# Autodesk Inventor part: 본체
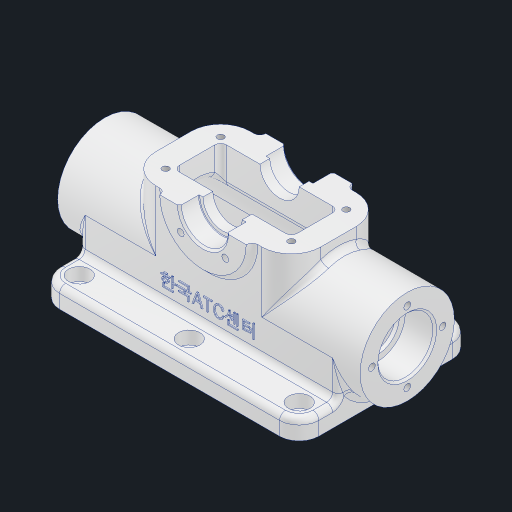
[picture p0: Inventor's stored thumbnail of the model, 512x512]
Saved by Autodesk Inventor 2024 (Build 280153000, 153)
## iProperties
Created: 2024-06
Part Number: 본체
Material: 알루미늄 6061
Document SubType Name: Modeling
Designer: kh_501
Density: 2.7 g/cm^3
Appearance: 알루미늄 - 평지
Mass: 551.028 g
Surface Area: 613.377 cm^2
Volume: 204.084 cm^3
Author: kh_501
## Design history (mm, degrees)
sketch "스케치1"
  geometry: L1 (66, 44)-(-66, 44); L2 (-66, 44)-(-66, -44); L3 (-66, -44)-(66, -44); L4 (66, -44)-(66, 44); L5 (66, 44)-(-66, -44); L6 (-66, 44)-(66, -44); 1 further point
  constraints: 12 end point, 2 midpoint, 2 parallel, 1 horizontal, 1 perpendicular
  dimensions: "d0" = 132 distance of L2.end L3.end; "d1" = 88 distance of L3.end L1.start
extrude "돌출1" new body sketch "스케치1" distance "d2" = 10; taper "d3" = 0 deg
sketch "스케치2"
  geometry: L1 (-77, 52)-(77, 52); L2 (77, 52)-(77, 28); L3 (77, 28)-(-77, 28); L4 (-77, 28)-(-77, 52); L5 (-66, 0)-(66, 0) reference; 3 further points
  constraints: 8 end point, 2 midpoint, 2 parallel, 1 horizontal, 1 perpendicular, 1 vertical alignment
  dimensions: "d4" = 28 distance between parallel lines of L5 L3; "d5" = 154 distance of L1.start L1.end; "d6" = 48 diameter of L1 L3
revolve "회전1" sketch "스케치2" stored, may be unused: angle "d7" = 90 deg
sketch "스케치3"
  geometry: L1 (-66, 44)-(-66, 15.875) reference; L2 (66, 15.875)-(66, 44) reference; L3 (77, 24)-(-77, 24) reference; L4 (77, -24)-(-77, -24) reference; L5 (-66, -15.875)-(-66, 15.875) reference; L6 (-66, -15.875)-(-66, -44) reference; L7 (66, 15.875)-(66, -15.875) reference; L8 (66, -44)-(66, 44) reference; L9 (-42, -24)-(42, -24); L10 (42, 24)-(-42, 24); 5 further points
  constraints: 4 end point, 1 horizontal, 1 parallel, 1 point on line
extrude "돌출2" join sketch "스케치3" stored distance "d9" = 18; taper "d10" = 0 deg
node "작업 평면1"
sketch "스케치4"
  geometry: L1 (-66, 24)-(66, 24) reference; L2 (-66, -24)-(66, -24) reference; L3 (-42, 24)-(42, 24); L4 (42, 24)-(42, -24); L5 (42, -24)-(-42, -24); L6 (-42, -24)-(-42, 24); L7 (-42, 24)-(42, -24); L8 (42, 24)-(-42, -24); 4 further points
  constraints: 12 end point, 2 midpoint, 2 parallel, 1 horizontal, 1 perpendicular, 1 point on line
  dimensions: "d12" = 84 distance between parallel lines of L6 L4
extrude "돌출3" join sketch "스케치4" stored distance "d13" = 10; taper "d14" = 0 deg
sketch "스케치5"
  geometry: L1 (-42, 59)-(42, 59) reference; C1 r 22 at (0, 59); 3 further points
  constraints: 1 centre point, 1 midpoint
  dimensions: "d15" = 44 diameter of C1
extrude "돌출4" join sketch "스케치5" stored distance "d16" = 54; taper "d17" = 0 deg
sketch "스케치6"
  geometry: L1 (0, -44)-(0, 44) reference; L2 (0, 18)-(28, 18); L3 (28, -18)-(0, -18); L4 (10, 24)-(28, 24) reference; A1 r 18 centre (28, 0) between (28, -18) and (28, 18); A2 r 24 centre (28, 0) between (28, -24) and (28, 24) reference; 2 further points
  constraints: 4 end point, 2 point on circle, 2 point on line, 2 tangent, 1 centre point, 1 coincident, 1 horizontal, 1 horizontal alignment, 1 midpoint, 1 perpendicular
  dimensions: "d18" = 6 distance between parallel lines of L4 L2
extrude "돌출5" cut sketch "스케치6" stored distance "d19" = 120; taper "d20" = 0 deg
fillet "모깎기1" dims "d21" = 15
sketch "스케치7"
  geometry: L1 (-42, 9)-(-42, -9) reference; L2 (42, -9)-(42, 9) reference; L3 (-22, 24)-(-27, 24) reference; L4 (27, 24)-(22, 24) reference; L5 (-27, -24)-(-22, -24) reference; L6 (22, -24)-(27, -24) reference; L7 (-22, -12)-(-27, -12); L8 (-30, -9)-(-30, 9); L9 (-27, 12)-(-22, 12); L10 (22, 12)-(27, 12); L11 (30, 9)-(30, -9); L12 (27, -12)-(22, -12); L13 (-22, 12)-(22, 12); L14 (-22, -12)-(22, -12); L15 (-32, -14)-(32, -14); L16 (32, -14)-(32, 14); L17 (32, 14)-(-32, 14); L18 (-32, 14)-(-32, -14); L19 (-32, -14)-(32, 14); L20 (32, -14)-(-32, 14); A1 r 15 centre (-27, 9) between (-27, 24) and (-42, 9) reference; A2 r 15 centre (-27, -9) between (-42, -9) and (-27, -24) reference; A3 r 15 centre (27, 9) between (42, 9) and (27, 24) reference; A4 r 15 centre (27, -9) between (27, -24) and (42, -9) reference; A5 r 3 centre (-27, -9) between (-30, -9) and (-27, -12); A6 r 3 centre (-27, 9) between (-27, 12) and (-30, 9); A7 r 3 centre (27, 9) between (30, 9) and (27, 12); A8 r 3 centre (27, -9) between (27, -12) and (30, -9); 5 further points
  constraints: 28 end point, 8 point on circle, 4 centre point, 4 coincident, 2 midpoint, 2 parallel, 1 horizontal, 1 perpendicular, 8 other
  dimensions: "d23" = 12 distance between parallel lines of L1 L8; "d24" = 12 distance between parallel lines of L2 L11; "d27" = 64 distance of L16.end L17.end; "d28" = 28 distance of L15.end L16.end
extrude "돌출6" cut sketch "스케치7" stored distance "d25" = 120; taper "d26" = 0 deg
hole "구멍1" sketch "스케치7" diameter "d29" = 3.45873; stored, may be unused: countersink angle "d33" = 90 deg, drill point angle "d35" = 120 deg; dims "d30" = 8, "d31" = 28, "d32" = 30, "d34" = 10
sketch "스케치8"
  geometry: A1 r 22 centre (0, 59) between (-22, 59) and (22, 59) reference; 2 further points
  constraints: 1 coincident
hole "구멍2" sketch "스케치8" at (0, 59) diameter "d36" = 20; stored, may be unused: countersink angle "d40" = 90 deg, drill point angle "d42" = 120 deg; dims "d37" = 8, "d38" = 24, "d39" = 10, "d41" = 20
sketch "스케치9"
  geometry: L1 (0, 59)-(0, 43); L2 (0, 59)-(-11.314, 47.686); L3 (0, 59)-(11.314, 47.686); A1 r 12 centre (0, 59) between (-12, 59) and (12, 59) reference; A2 r 16 centre (0, 59) between (0, 43) and (-11.314, 47.686); 3 further points
  constraints: 6 end point, 3 coincident, 3 point on circle, 1 centre point, 1 vertical
  dimensions: "d43" = 32 diameter of A2; "d44" = 45 deg angle of L2 L1; "d45" = 45 deg angle of L3 L1
hole "구멍3" sketch "스케치9" at (-11.314, 47.686), (11.314, 47.686) diameter "d46" = 3.45873; stored, may be unused: countersink angle "d50" = 90 deg, drill point angle "d52" = 118 deg; dims "d47" = 8, "d48" = 24, "d49" = 10, "d51" = 10
sketch "스케치10" dims "d53" = 36
  geometry: L1 (0, 0)-(0, 18); C1 r 24 at (0, 0) reference; 2 further points
  constraints: 2 coincident, 2 end point, 1 vertical, 1 vertical alignment, 2 other
hole "구멍4" sketch "스케치10" at (0, 18) diameter "d54" = 3.45873; stored, may be unused: countersink angle "d58" = 90 deg, drill point angle "d60" = 118 deg; dims "d55" = 8, "d56" = 4, "d57" = 2, "d59" = 10
sketch "스케치11"
  geometry: C1 r 24 at (0, 0) reference; 2 further points
  constraints: 1 coincident
hole "구멍5" sketch "스케치11" at (0, 0) diameter "d61" = 22; stored, may be unused: countersink angle "d65" = 90 deg, drill point angle "d67" = 118 deg; dims "d62" = 8, "d63" = 28, "d64" = 15, "d66" = 10
fillet "모깎기2" dims "d71" = 10
sketch "스케치12"
  geometry: L1 (-56, -34)-(56, -34); L2 (56, -34)-(56, 34); L3 (56, 34)-(-56, 34); L4 (-56, 34)-(-56, -34); L5 (-56, -34)-(56, 34); L6 (56, -34)-(-56, 34); L7 (0, 34)-(0, -34); 7 further points
  constraints: 14 end point, 6 coincident, 4 midpoint, 2 parallel, 1 horizontal, 1 perpendicular
  dimensions: "d72" = 112 distance of L2.end L3.end; "d73" = 68 distance of L1.end L2.end
hole "구멍6" sketch "스케치12" at (-56, 34), (0, 34), (56, 34), (56, -34), (0, -34), (-56, -34) diameter "d74" = 6.6; stored, may be unused: countersink angle "d78" = 90 deg, drill point angle "d80" = 118 deg; dims "d75" = 6, "d76" = 11, "d77" = 6.6, "d79" = 8
sketch "스케치13" dims "d0" = 132, "d1" = 88
  geometry: L1 (10, -10)-(122, -10) reference; 3 further points
  constraints: 1 midpoint, 1 vertical alignment, 1 other
  dimensions: "d81" = 20 distance from line of L1 point (66, 10)
feature "엠보싱1" sketch "스케치13" dims "d0" = 132, "d1" = 88, "d82" = 0.5, "d83" = 0
fillet "모깎기3" dims "d84" = 0.3
fillet "모깎기4" dims "d85" = 3
fillet "모깎기5" dims "d86" = 3
fillet "모깎기6" dims "d87" = 3
chamfer "모따기1" distance "d88" = 1; stored, may be unused: second distance "d89" = 2, angle "d90" = 45 deg
node "솔리드1"
mirror "미러1"
pattern_circular "원형 패턴1" dims angle "d69" = 360 deg
mirror "미러2"
feature "A9D066F2-1C7D-4E18-AEED-F7BC21143FA4" dims "d36" = 20, "d37" = 8, "d38" = 24, "d39" = 10, "d40" = 90 deg, "d41" = 20, "d42" = 120 deg
other parameters: "d11" = 59
